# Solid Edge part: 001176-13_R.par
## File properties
Last saved by: morva
Revision: 82
Accuracy: 0.990
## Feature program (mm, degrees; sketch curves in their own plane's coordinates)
body "unnamed Body 1"
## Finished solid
Body 1: solid body, 26 faces, 53 edges, 31 vertices.
  Faces by surface: cone 9, plane 9, cylinder 4, torus 4
  Edges by curve: circle 23, curve on surface 15, line 13, spline 2
Bounding box of the edges (mm; curved faces can reach further): 12.974 x 30.279 x 16.776, from (380.0694, 377.3914, 151.5702) to (393.0438, 407.6704, 168.3464).
Cylindrical faces by radius (mm): R3 x2, R5 x2
Conical faces (half-angle, radius in mm at the cone's reference point): 45 deg R2.8868 x7, 45 deg R3 x2
Toroidal faces (ring radius, tube radius in mm): R0.3636 r5.2939 x2, R4 r1 x2
Planar faces by outward normal: oblique 9
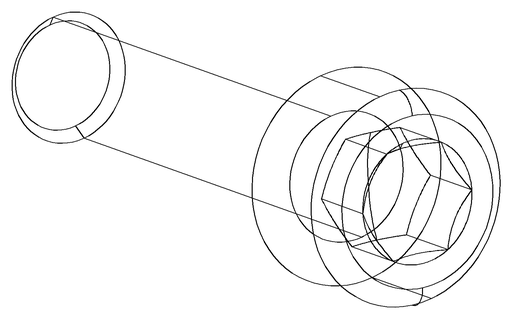
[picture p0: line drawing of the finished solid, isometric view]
